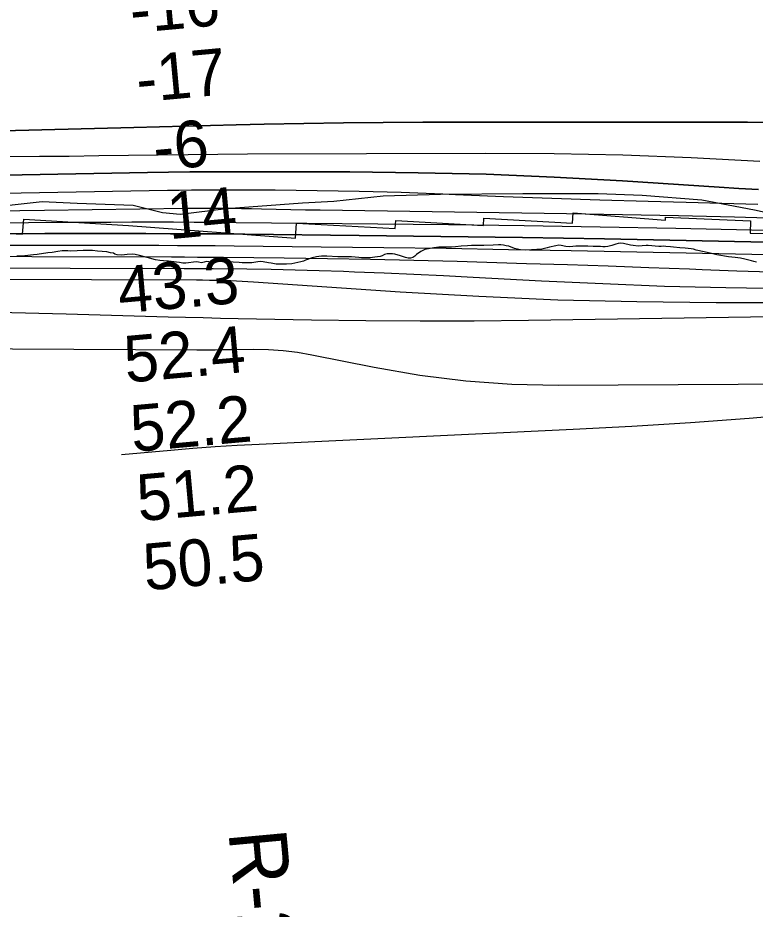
# Model space of a CAD drawing. Extents: x 3192986 to 3230865, y 867483 to 892886.
# Drawn here: x 3200491 to 3201551, y 876124 to 877406 of the extents above; entities that cross this region are included whole.
import ezdxf

# ---------------------------------------------------------------- set-up
doc = ezdxf.new("R2010")
doc.units = 0
for name, color, linetype in [('V-RIVR-EDGE', 7, 'Continuous'), ('V-RIVR-RANG', 7, 'Continuous'), ('V-RIVR-RANG-IDEN', 7, 'Continuous'), ('V-RRAP-RVMT', 7, 'Continuous'), ('V-SITE-VEGE', 7, 'Continuous'), ('V-TOPO-DPTH', 7, 'Continuous'), ('V-TOPO-MAJR', 7, 'Continuous'), ('V-TOPO-MINR', 7, 'Continuous'), ('V-TOPO-WATR', 7, 'Continuous')]:
    doc.layers.add(name, color=color, linetype=linetype)

msp = doc.modelspace()

# ---------------------------------------------------------------- linework, layer by layer
at = {"layer": 'V-RIVR-EDGE'}
msp.add_lwpolyline([(3200469.8, 877135.2), (3200526.1, 877141.7), (3200576.1, 877139.2), (3200656.7, 877136.2), (3200698.7, 877125.6), (3200724.4, 877123.1), (3200790.7, 877131.5), (3200899.9, 877139.4), (3200945.2, 877142.1), (3201015.8, 877149.6), (3201098.3, 877152.2), (3201216.6, 877152.9), (3201324.9, 877153.1), (3201388.3, 877150.6), (3201474.1, 877144.1), (3201549.9, 877129.7), (3201621.9, 877113.7)], dxfattribs=at)
at = {"layer": 'V-RRAP-RVMT'}
for p, q in [((3201288.2, 877110.2), (3201289.2, 877125.2)), ((3201289.2, 877125.2), (3201421.6, 877114.5)), ((3200497.5, 877094.5), (3200499.7, 877116.2)), ((3200499.7, 877116.2), (3200650.1, 877107)), ((3200889.9, 877089), (3200891.6, 877110.3)), ((3200891.6, 877110.3), (3201033.3, 877102.7)), ((3201033.3, 877102.7), (3201034, 877114)), ((3201034, 877114), (3201160, 877107.1)), ((3201160, 877107.1), (3201160.5, 877117.3)), ((3201160.5, 877117.3), (3201288.2, 877110.2)), ((3201421.6, 877114.5), (3201422, 877119)), ((3201422, 877119), (3201544.1, 877113.9)), ((3201544.1, 877113.9), (3201543.5, 877096)), ((3200366.2, 877102.1), (3200497.5, 877094.5)), ((3200650.1, 877107), (3200889.9, 877089)), ((3201543.5, 877096), (3201659.8, 877092.6))]:
    msp.add_line(p, q, dxfattribs=at)
at = {"layer": 'V-SITE-VEGE'}
for p, q in [((3201076, 877072.4), (3201070.3, 877069.5)), ((3201088.6, 877074.9), (3201076, 877072.4)), ((3201095.8, 877075.9), (3201088.6, 877074.9)), ((3201102.1, 877076), (3201095.8, 877075.9)), ((3201110.3, 877075.8), (3201102.1, 877076)), ((3201114.1, 877075.9), (3201110.3, 877075.8)), ((3201119.8, 877076.3), (3201114.1, 877075.9)), ((3201127.9, 877077.3), (3201119.8, 877076.3)), ((3201137.4, 877078), (3201127.9, 877077.3)), ((3201142.9, 877078.2), (3201137.4, 877078)), ((3201156.8, 877078.2), (3201142.9, 877078.2)), ((3201160.8, 877078.3), (3201156.8, 877078.2)), ((3201174.3, 877078.8), (3201160.8, 877078.3)), ((3201182, 877079.4), (3201174.3, 877078.8)), ((3201185.3, 877079.2), (3201182, 877079.4)), ((3201188.8, 877078.8), (3201185.3, 877079.2)), ((3201192.8, 877078), (3201188.8, 877078.8)), ((3201196.7, 877077.1), (3201192.8, 877078)), ((3201204.9, 877074), (3201196.7, 877077.1)), ((3201213.5, 877072), (3201204.9, 877074)), ((3201220.6, 877071.6), (3201213.5, 877072)), ((3201229.4, 877071.9), (3201220.6, 877071.6)), ((3201244, 877073.2), (3201229.4, 877071.9)), ((3201247.9, 877073.9), (3201244, 877073.2)), ((3201251.8, 877074.8), (3201247.9, 877073.9)), ((3201255.2, 877075.8), (3201251.8, 877074.8)), ((3201264.3, 877077.7), (3201255.2, 877075.8)), ((3201268.7, 877078.5), (3201264.3, 877077.7)), ((3201272, 877078.2), (3201268.7, 877078.5)), ((3201278.6, 877076.6), (3201272, 877078.2)), ((3201284.1, 877076.2), (3201278.6, 877076.6)), ((3201293.1, 877077.5), (3201284.1, 877076.2)), ((3201296.1, 877077.5), (3201293.1, 877077.5)), ((3201299.4, 877077.2), (3201296.1, 877077.5)), ((3201310, 877077.2), (3201299.4, 877077.2)), ((3201318, 877076.8), (3201310, 877077.2)), ((3201328.2, 877076.8), (3201318, 877076.8)), ((3201331.9, 877076.3), (3201328.2, 877076.8)), ((3201335.3, 877076.3), (3201331.9, 877076.3)), ((3201338.7, 877076.7), (3201335.3, 877076.3)), ((3201344.7, 877078.1), (3201338.7, 877076.7)), ((3201347.5, 877079.3), (3201344.7, 877078.1)), ((3201350.4, 877080.3), (3201347.5, 877079.3)), ((3201353.8, 877081.1), (3201350.4, 877080.3)), ((3201357.6, 877081.4), (3201353.8, 877081.1)), ((3201361.2, 877080.9), (3201357.6, 877081.4)), ((3201371.6, 877078.7), (3201361.2, 877080.9)), ((3201375.3, 877078.4), (3201371.6, 877078.7)), ((3201382.4, 877077.4), (3201375.3, 877078.4)), ((3201393.8, 877078.3), (3201382.4, 877077.4)), ((3201397.1, 877078.3), (3201393.8, 877078.3)), ((3201412.2, 877076.9), (3201397.1, 877078.3)), ((3201415.6, 877076.9), (3201412.2, 877076.9)), ((3201419.1, 877077.2), (3201415.6, 877076.9)), ((3201422.1, 877077), (3201419.1, 877077.2)), ((3201429.1, 877076.1), (3201422.1, 877077)), ((3201433.2, 877075.8), (3201429.1, 877076.1)), ((3201442.5, 877074.8), (3201433.2, 877075.8)), ((3201450.2, 877074.5), (3201442.5, 877074.8)), ((3201458.7, 877073.4), (3201450.2, 877074.5)), ((3201462.2, 877072.8), (3201458.7, 877073.4)), ((3201465.7, 877071.6), (3201462.2, 877072.8)), ((3201477.2, 877069), (3201465.7, 877071.6)), ((3200500.9, 877063.4), (3200489.7, 877063.1)), ((3200513.6, 877064.6), (3200500.9, 877063.4)), ((3200518.7, 877065.2), (3200513.6, 877064.6)), ((3200533.8, 877067.5), (3200518.7, 877065.2)), ((3200540.3, 877068), (3200533.8, 877067.5)), ((3200548.4, 877069.6), (3200540.3, 877068)), ((3200554.8, 877070.4), (3200548.4, 877069.6)), ((3200562.7, 877070.5), (3200554.8, 877070.4)), ((3200566, 877070.3), (3200562.7, 877070.5)), ((3200576.1, 877070.7), (3200566, 877070.3)), ((3200584.8, 877071), (3200576.1, 877070.7)), ((3200591.5, 877071), (3200584.8, 877071)), ((3200598.1, 877071.2), (3200591.5, 877071)), ((3200605.2, 877070.2), (3200598.1, 877071.2)), ((3200619, 877068.9), (3200605.2, 877070.2)), ((3200624.2, 877067.9), (3200619, 877068.9)), ((3200628.5, 877067.4), (3200624.2, 877067.9)), ((3200630.5, 877065.7), (3200628.5, 877067.4)), ((3200633.7, 877064.6), (3200630.5, 877065.7)), ((3200640.3, 877064.4), (3200633.7, 877064.6)), ((3200648.1, 877065.3), (3200640.3, 877064.4)), ((3200655.1, 877065.6), (3200648.1, 877065.3)), ((3200659.4, 877065.1), (3200655.1, 877065.6)), ((3200665.8, 877063.9), (3200659.4, 877065.1)), ((3200676.8, 877061.1), (3200665.8, 877063.9)), ((3200689, 877057.8), (3200676.8, 877061.1)), ((3200914.1, 877060.3), (3200904.6, 877057.2)), ((3200920.2, 877061.9), (3200914.1, 877060.3)), ((3200923.6, 877062.2), (3200920.2, 877061.9)), ((3200927.6, 877062.7), (3200923.6, 877062.2)), ((3200935, 877062.9), (3200927.6, 877062.7)), ((3200950.8, 877062.1), (3200935, 877062.9)), ((3200956.5, 877061.9), (3200950.8, 877062.1)), ((3200970.6, 877062), (3200956.5, 877061.9)), ((3200980.8, 877060.9), (3200970.6, 877062)), ((3200985, 877060.7), (3200980.8, 877060.9)), ((3200988.7, 877060.3), (3200985, 877060.7)), ((3200997.5, 877060.4), (3200988.7, 877060.3)), ((3201004.1, 877061.5), (3200997.5, 877060.4)), ((3201011.5, 877062.2), (3201004.1, 877061.5)), ((3201014.6, 877063.3), (3201011.5, 877062.2)), ((3201018, 877065.2), (3201014.6, 877063.3)), ((3201021.6, 877066.3), (3201018, 877065.2)), ((3201025.3, 877066.4), (3201021.6, 877066.3)), ((3201029.4, 877066.2), (3201025.3, 877066.4)), ((3201033, 877065.8), (3201029.4, 877066.2)), ((3201040.7, 877063.6), (3201033, 877065.8)), ((3201048.3, 877060.9), (3201040.7, 877063.6)), ((3201051.9, 877060), (3201048.3, 877060.9)), ((3201055.2, 877060.2), (3201051.9, 877060)), ((3201058.4, 877061.2), (3201055.2, 877060.2)), ((3201061.4, 877063.1), (3201058.4, 877061.2)), ((3201064.1, 877065.2), (3201061.4, 877063.1)), ((3201070.3, 877069.5), (3201064.1, 877065.2)), ((3201487.8, 877066.9), (3201477.2, 877069)), ((3201495.6, 877065), (3201487.8, 877066.9)), ((3201512.5, 877062), (3201495.6, 877065)), ((3201522.1, 877061.2), (3201512.5, 877062)), ((3201529.4, 877060), (3201522.1, 877061.2)), ((3201535.7, 877058.8), (3201529.4, 877060)), ((3201545.2, 877056.2), (3201535.7, 877058.8)), ((3200694.8, 877056.8), (3200689, 877057.8)), ((3200700.3, 877056.1), (3200694.8, 877056.8)), ((3200704.4, 877055.9), (3200700.3, 877056.1)), ((3200707.4, 877055.9), (3200704.4, 877055.9)), ((3200718.9, 877054.5), (3200707.4, 877055.9)), ((3200723.4, 877053.6), (3200718.9, 877054.5)), ((3200728.1, 877053), (3200723.4, 877053.6)), ((3200732.6, 877053), (3200728.1, 877053)), ((3200747.3, 877054.9), (3200732.6, 877053)), ((3200750.8, 877054.4), (3200747.3, 877054.9)), ((3200754.8, 877053.4), (3200750.8, 877054.4)), ((3200758.6, 877054.3), (3200754.8, 877053.4)), ((3200762.2, 877055), (3200758.6, 877054.3)), ((3200769.2, 877054.3), (3200762.2, 877055)), ((3200772.8, 877054.3), (3200769.2, 877054.3)), ((3200782.7, 877056), (3200772.8, 877054.3)), ((3200787.5, 877055.8), (3200782.7, 877056)), ((3200797, 877054.9), (3200787.5, 877055.8)), ((3200800.3, 877054.3), (3200797, 877054.9)), ((3200809, 877053.6), (3200800.3, 877054.3)), ((3200813.5, 877053.3), (3200809, 877053.6)), ((3200820.3, 877053.2), (3200813.5, 877053.3)), ((3200827, 877053.3), (3200820.3, 877053.2)), ((3200836.1, 877054.7), (3200827, 877053.3)), ((3200840.3, 877055.1), (3200836.1, 877054.7)), ((3200843.6, 877054.9), (3200840.3, 877055.1)), ((3200851.4, 877053.5), (3200843.6, 877054.9)), ((3200854.8, 877052.7), (3200851.4, 877053.5)), ((3200862.4, 877051.6), (3200854.8, 877052.7)), ((3200877, 877051.5), (3200862.4, 877051.6)), ((3200884.9, 877052.1), (3200877, 877051.5)), ((3200897.6, 877054.6), (3200884.9, 877052.1)), ((3200901.7, 877055.9), (3200897.6, 877054.6)), ((3200904.6, 877057.2), (3200901.7, 877055.9)), ((3201548.6, 877055.2), (3201545.2, 877056.2)), ((3201552.7, 877054.2), (3201548.6, 877055.2))]:
    msp.add_line(p, q, dxfattribs=at)
at = {"layer": 'V-TOPO-DPTH'}
for points in [[(3199901.5, 877228.6), (3200657.5, 877247.8), (3200694.3, 877248.7), (3200731.2, 877249.7), (3200768, 877250.6), (3200804.9, 877251.6), (3200845.2, 877252.6), (3200902.2, 877253.8), (3200959.2, 877254.8), (3201016.2, 877255.3), (3201073.2, 877255.5), (3201413.5, 877255.7), (3201455.6, 877255.6), (3201497.7, 877255.6), (3201539.7, 877255.4), (3201581.8, 877255.3)], [(3201581.8, 877255.3), (3201539.7, 877255.4), (3201497.7, 877255.6), (3201455.6, 877255.6), (3201413.5, 877255.7), (3201073.2, 877255.5), (3201016.2, 877255.3), (3200959.2, 877254.8), (3200902.2, 877253.8), (3200845.2, 877252.6), (3200804.9, 877251.6), (3200768, 877250.6), (3200731.2, 877249.7), (3200694.3, 877248.7), (3200657.5, 877247.8), (3199901.5, 877228.6)], [(3201555.4, 877158.7), (3201527.2, 877160.2), (3201499, 877161.9), (3201359.8, 877171), (3201262, 877176.4), (3201164.2, 877180.6), (3201066.2, 877182.9), (3200968.3, 877184), (3200798.4, 877184.2), (3200768.1, 877184.1), (3200737.9, 877184), (3200707.7, 877183.6), (3200677.4, 877183.2), (3200497, 877180), (3200377.2, 877178.4)], [(3201555.4, 877158.7), (3201527.2, 877160.2), (3201499, 877161.9), (3201359.8, 877171), (3201262, 877176.4), (3201164.2, 877180.6), (3201066.2, 877182.9), (3200968.3, 877184), (3200798.4, 877184.2), (3200768.1, 877184.1), (3200737.9, 877184), (3200707.7, 877183.6), (3200677.4, 877183.2), (3200497, 877180), (3200377.2, 877178.4)], [(3200422.6, 877127.4), (3200529.3, 877128.9), (3200734.7, 877131.9), (3200738.7, 877131.9), (3200742.7, 877132), (3200746.7, 877132), (3200750.7, 877132), (3200770.7, 877131.9), (3200784.7, 877131.8), (3200798.6, 877131.7), (3200812.6, 877131.5), (3200826.6, 877131.2), (3200841, 877130.9), (3200862.1, 877130.4), (3200883.3, 877130), (3200904.5, 877129.6), (3200925.6, 877129.3), (3201279.5, 877124.2), (3201359.9, 877122.9), (3201440.3, 877121.3), (3201520.8, 877119.4), (3201601.2, 877117.2)], [(3200422.6, 877127.4), (3200529.3, 877128.9), (3200734.7, 877131.9), (3200738.7, 877131.9), (3200742.7, 877132), (3200746.7, 877132), (3200750.7, 877132), (3200770.7, 877131.9), (3200784.7, 877131.8), (3200798.6, 877131.7), (3200812.6, 877131.5), (3200826.6, 877131.2), (3200841, 877130.9), (3200862.1, 877130.4), (3200883.3, 877130), (3200904.5, 877129.6), (3200925.6, 877129.3), (3201279.5, 877124.2), (3201359.9, 877122.9), (3201440.3, 877121.3), (3201520.8, 877119.4), (3201601.2, 877117.2)], [(3203371.9, 876886.2), (3202573.8, 876856.3), (3202560.8, 876856.1), (3202547.8, 876856.2), (3201799.1, 877076.7), (3201776.7, 877078.1), (3201770.9, 877078.4), (3201765.1, 877078.6), (3201759.3, 877078.8), (3201753.5, 877079), (3201451.6, 877085.3), (3201334.1, 877087.6), (3201216.5, 877089.6), (3201098.9, 877091.3), (3200981.3, 877092.7), (3200817.2, 877094.5), (3200781.6, 877094.8), (3200746.1, 877095), (3200710.5, 877095.2), (3200675, 877095.3), (3200601.8, 877095.3), (3200529.7, 877095.3), (3200457.5, 877095.1)]]:
    msp.add_lwpolyline(points, dxfattribs=at)
at = {"layer": 'V-TOPO-MAJR'}
msp.add_lwpolyline([(3200073.9, 877047.1), (3200729.8, 877045.3), (3200740.2, 877045.2), (3200750.7, 877045.2), (3200761.1, 877045.1), (3200771.6, 877045), (3200820.1, 877044.5), (3200854.8, 877044), (3200889.5, 877043.4), (3200924.2, 877042.4), (3200958.9, 877041.2), (3200974.8, 877040.6), (3201017.4, 877038.9), (3201060.1, 877037.1), (3201102.7, 877035), (3201145.3, 877032.8), (3201243.6, 877027.6), (3201331.9, 877023.4), (3201420.3, 877020), (3201508.6, 877017.7), (3201597, 877016.2)], dxfattribs=at)
at = {"layer": 'V-TOPO-MINR'}
for points in [[(3199901.5, 877228.6), (3200657.5, 877247.8), (3200694.3, 877248.7), (3200731.2, 877249.7), (3200768, 877250.6), (3200804.9, 877251.6), (3200845.2, 877252.6), (3200902.2, 877253.8), (3200959.2, 877254.8), (3201016.2, 877255.3), (3201073.2, 877255.5), (3201413.5, 877255.7), (3201455.6, 877255.6), (3201497.7, 877255.6), (3201539.7, 877255.4), (3201581.8, 877255.3)], [(3200479.2, 877206.4), (3200522, 877206.6), (3200564.7, 877206.9), (3200607.4, 877207.4), (3200650.1, 877208.1), (3200692.8, 877208.7), (3200735.6, 877209.3), (3200778.3, 877209.6), (3200821, 877209.9), (3201163, 877210.9), (3201261.7, 877210.3), (3201360.3, 877208.4), (3201458.9, 877204.6), (3201557.4, 877199.5)], [(3200377.2, 877178.4), (3200497, 877180), (3200677.4, 877183.2), (3200707.7, 877183.6), (3200737.9, 877184), (3200768.1, 877184.1), (3200798.4, 877184.2), (3200968.3, 877184), (3201066.2, 877182.9), (3201164.2, 877180.6), (3201262, 877176.4), (3201359.8, 877171), (3201499, 877161.9), (3201527.2, 877160.2), (3201555.4, 877158.7)], [(3200022.2, 877145.5), (3200705.8, 877157.7), (3200723, 877158), (3200740.3, 877158.2), (3200757.5, 877158.3), (3200774.8, 877158.3), (3200860.9, 877158.1), (3200921.1, 877157.5), (3200981.4, 877156.5), (3201041.7, 877154.8), (3201101.9, 877152.5), (3201119.8, 877151.8), (3201189, 877148.9), (3201258.3, 877146.3), (3201327.5, 877144.1), (3201396.7, 877142.2), (3201451.3, 877140.7), (3201502.8, 877139.3), (3201554.3, 877137.9)], [(3199803.6, 877105.5), (3200564.6, 877111.6), (3200594.6, 877111.8), (3200624.6, 877112), (3200654.6, 877112.1), (3200684.6, 877112.1), (3200714.5, 877112.1), (3200744.5, 877112), (3200774.5, 877111.7), (3200804.5, 877111.5), (3201109.8, 877108.3), (3201218.7, 877106.9), (3201327.7, 877105.2), (3201436.7, 877103), (3201545.6, 877100.6), (3201735.5, 877095.9), (3201749.5, 877095.4), (3201763.6, 877094.9), (3201777.6, 877094.2), (3201791.6, 877093.4), (3201844.4, 877090.1), (3202501.3, 876922.5), (3202513.3, 876921.3), (3202653.3, 876909.6)], [(3200457.5, 877095.1), (3200529.7, 877095.3), (3200601.8, 877095.3), (3200675, 877095.3), (3200710.5, 877095.2), (3200746.1, 877095), (3200781.6, 877094.8), (3200817.2, 877094.5), (3200981.3, 877092.7), (3201098.9, 877091.3), (3201216.5, 877089.6), (3201334.1, 877087.6), (3201451.6, 877085.3), (3201753.5, 877079), (3201759.3, 877078.8), (3201765.1, 877078.6), (3201770.9, 877078.4), (3201776.7, 877078.1), (3201799.1, 877076.7), (3202547.8, 876856.2), (3202560.8, 876856.1), (3202573.8, 876856.3), (3203371.9, 876886.2)], [(3200407.4, 877078.8), (3200520.8, 877078.7), (3200693.4, 877078.5), (3200720.5, 877078.4), (3200747.6, 877078.3), (3200774.7, 877078.1), (3200801.9, 877077.9), (3200927.1, 877076.5), (3201016.8, 877075.4), (3201106.5, 877074.2), (3201196.3, 877072.6), (3201286, 877070.9), (3201640.4, 877063.7)], [(3200309.6, 877062.7), (3200711.7, 877061.9), (3200730.4, 877061.8), (3200749.2, 877061.7), (3200767.9, 877061.6), (3200786.7, 877061.4), (3200873.6, 877060.5), (3200935.8, 877059.7), (3200998, 877058.6), (3201060.2, 877057.2), (3201122.4, 877055.6), (3201222.2, 877052.6), (3201280.7, 877050.8), (3201339.3, 877048.9), (3201397.8, 877046.8), (3201456.4, 877044.5), (3201474.7, 877043.8), (3201524.1, 877041.9), (3201573.4, 877040.2)], [(3199842.6, 877031.9), (3200747.9, 877028.8), (3200752.2, 877028.7), (3200754.4, 877028.7), (3200756.5, 877028.7), (3200766.6, 877028.6), (3200773.8, 877028.5), (3200781, 877028.3), (3200788.2, 877028.1), (3200795.4, 877027.8), (3200797.2, 877027.7), (3200805.2, 877027.3), (3200813.3, 877026.9), (3200821.4, 877026.4), (3200829.4, 877025.9), (3201040.2, 877011.7), (3201153.6, 877005.2), (3201267.1, 877000.2), (3201380.7, 876997.5), (3201494.4, 876996.3), (3201748.2, 876996.2)], [(3200462.1, 876982.3), (3200560.4, 876980), (3200707, 876975.8), (3200732.1, 876975.1), (3200757.2, 876974.5), (3200782.3, 876973.9), (3200807.4, 876973.4), (3200913.1, 876971.4), (3200991.1, 876970.3), (3201069, 876969.7), (3201147, 876970), (3201224.9, 876970.8), (3201767.9, 876979.1)], [(3199864.2, 876933), (3200748.2, 876928.3), (3200754.8, 876928.3), (3200761.4, 876928.3), (3200768.1, 876928.3), (3200774.7, 876928.4), (3200781.4, 876928.5), (3200788, 876928.6), (3200794.7, 876928.6), (3200801.3, 876928.7), (3200830.2, 876929.1), (3200851.2, 876928.6), (3200872.1, 876927.3), (3200892.9, 876924.7), (3200913.6, 876921.2), (3201003.1, 876903.1), (3201068.8, 876891.9), (3201134.7, 876883.5), (3201201, 876879.1), (3201267.5, 876877.4), (3201784.9, 876880.3)], [(3201799, 876870.6), (3201801.1, 876869.2), (3201801.5, 876868.9), (3201801.7, 876868.5), (3201801.7, 876868.1), (3201801.6, 876867.6), (3201798.3, 876860.2), (3201796, 876856.6), (3201793.1, 876853.7), (3201789.5, 876852), (3201785.3, 876850.9), (3201626.2, 876836.6), (3201541.9, 876829.6), (3201457.6, 876823.3), (3201373.3, 876818.1), (3201288.9, 876813.6), (3200838, 876792.3), (3200806.2, 876790.6), (3200774.3, 876788.6), (3200742.4, 876786.3), (3200710.6, 876783.6), (3200640, 876777.4)]]:
    msp.add_lwpolyline(points, dxfattribs=at)
at = {"layer": 'V-TOPO-WATR'}
msp.add_lwpolyline([(3200422.6, 877127.4), (3200529.3, 877128.9), (3200734.7, 877131.9), (3200738.7, 877131.9), (3200742.7, 877132), (3200746.7, 877132), (3200750.7, 877132), (3200770.7, 877131.9), (3200784.7, 877131.8), (3200798.6, 877131.7), (3200812.6, 877131.5), (3200826.6, 877131.2), (3200841, 877130.9), (3200862.1, 877130.4), (3200883.3, 877130), (3200904.5, 877129.6), (3200925.6, 877129.3), (3201279.5, 877124.2), (3201359.9, 877122.9), (3201440.3, 877121.3), (3201520.8, 877119.4), (3201601.2, 877117.2)], dxfattribs=at)

# ---------------------------------------------------------------- texts
at = {"layer": 'V-RIVR-RANG'}
for s, rotation, p in [('-16', 5.2795, (3200654.7, 877383.4)), ('-17', 5.2795, (3200663.8, 877283.9)), ('-6', 5.2795, (3200688.2, 877185.7)), ('14', 5.2795, (3200708.7, 877087.2)), ('43.3', 5.1183, (3200637.4, 876980.5)), ('52.4', 5.1183, (3200646.5, 876880.9)), ('52.2', 5.1183, (3200655.7, 876781.3)), ('51.2', 5.1183, (3200664.9, 876681.7)), ('50.5', 5.1183, (3200674, 876582.2))]:
    msp.add_text(s, height=67, rotation=rotation, dxfattribs=at).set_placement(p)
at = {"layer": 'V-RIVR-RANG-IDEN'}
msp.add_text('R-294.15', height=83, rotation=275.2571, dxfattribs=at).set_placement((3200793.5, 876235.1))

doc.saveas('drawing.dxf')
